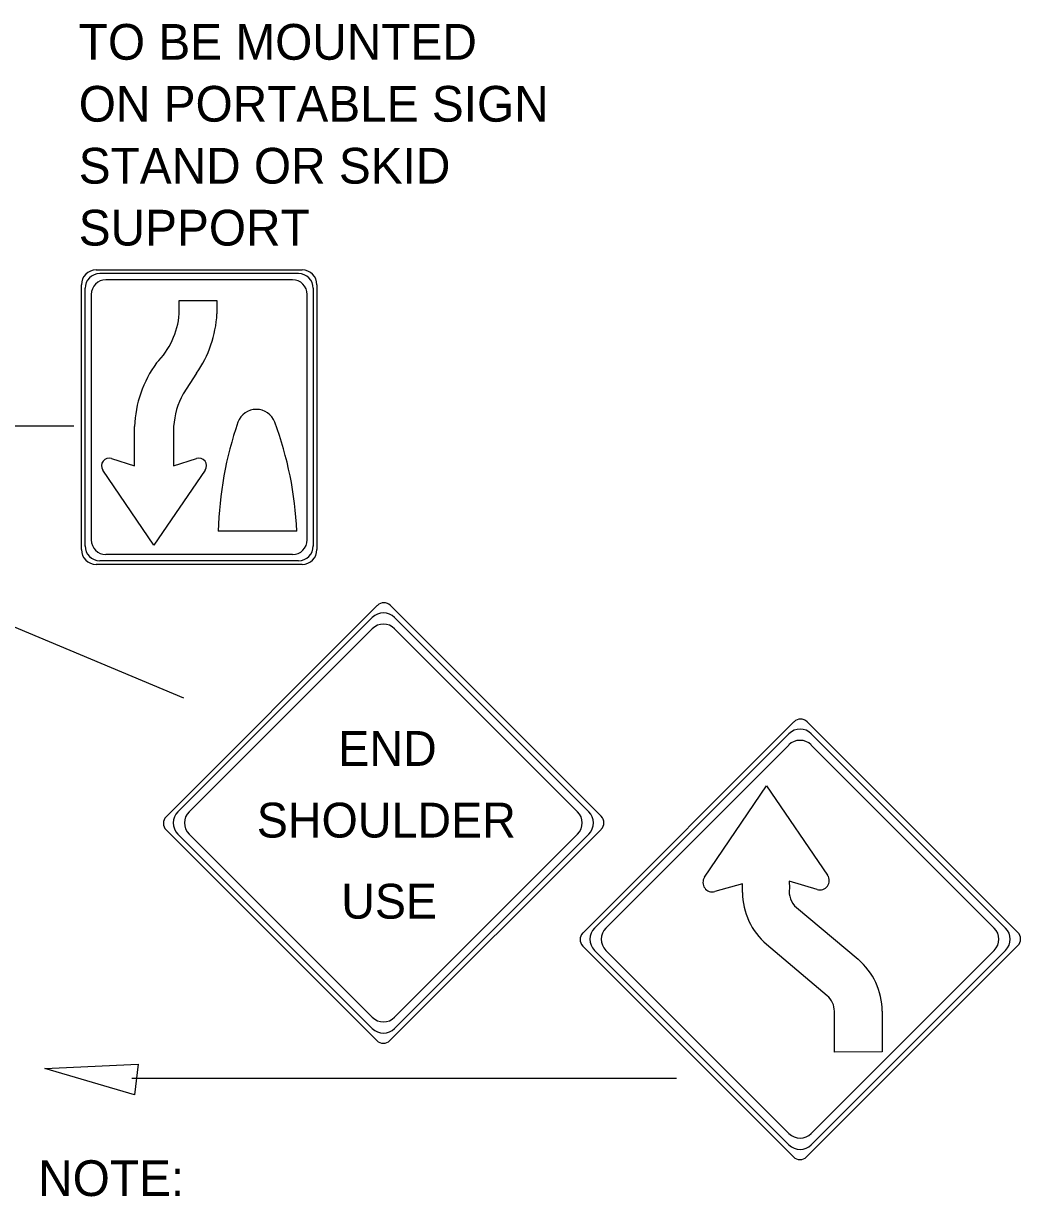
# Model space of a CAD drawing. Extents: x 1531.35 to 1538.58, y 1529.59 to 1539.23.
# Drawn here: x 1536.808 to 1538.482, y 1535.367 to 1537.337 of the extents above; entities that cross this region are included whole.
import ezdxf

# ---------------------------------------------------------------- set-up
doc = ezdxf.new("R2010")
doc.units = 0
for name, color, linetype in [('DETL-DIMS', 7, 'Continuous'), ('DETL-LINE', 7, 'Continuous'), ('DETL-NOTE', 7, 'Continuous')]:
    doc.layers.add(name, color=color, linetype=linetype)

msp = doc.modelspace()

# ---------------------------------------------------------------- linework, layer by layer
at = {"layer": 'DETL-DIMS'}
for p, q in [((1536.5902, 1536.6615), (1536.8925, 1536.6616)), ((1536.755, 1536.3393), (1537.0765, 1536.2049)), ((1537.9041, 1535.5657), (1536.9894, 1535.5658))]:
    msp.add_line(p, q, dxfattribs=at)
msp.add_lwpolyline([(1537.0003, 1535.5897), (1536.9941, 1535.5384), (1536.8433, 1535.5825)], close=True, dxfattribs=at)
at = {"layer": 'DETL-LINE'}
for p, q in [((1536.9296, 1536.9233), (1537.2757, 1536.9233)), ((1537.2696, 1536.9172), (1536.9359, 1536.9172)), ((1536.9049, 1536.4536), (1536.9049, 1536.8985)), ((1537.2592, 1536.9068), (1536.9461, 1536.9068)), ((1537.3004, 1536.8985), (1537.3004, 1536.4536)), ((1536.9112, 1536.4597), (1536.9112, 1536.8925)), ((1536.9214, 1536.8821), (1536.9214, 1536.4701)), ((1537.2839, 1536.4701), (1537.2839, 1536.8821)), ((1537.2943, 1536.8925), (1537.2943, 1536.4597)), ((1537.0694, 1536.872), (1537.1326, 1536.872)), ((1537.0694, 1536.8496), (1537.0694, 1536.872)), ((1537.1326, 1536.872), (1537.1326, 1536.8496)), ((1537.0982, 1536.7497), (1537.076, 1536.7151)), ((1536.9939, 1536.5945), (1536.9939, 1536.6604)), ((1537.0598, 1536.6604), (1537.0598, 1536.5945)), ((1536.9556, 1536.6069), (1536.994, 1536.5943)), ((1537.0598, 1536.5943), (1537.0982, 1536.6069)), ((1537.0268, 1536.4609), (1536.9408, 1536.5873)), ((1537.1129, 1536.5873), (1537.0268, 1536.4609)), ((1537.2666, 1536.4846), (1537.1348, 1536.4846)), ((1537.2592, 1536.4453), (1536.9461, 1536.4453)), ((1537.2757, 1536.4289), (1536.9296, 1536.4289)), ((1537.2696, 1536.435), (1536.9359, 1536.435)), ((1537.4018, 1536.3599), (1537.0471, 1536.0052)), ((1537.7777, 1536.0059), (1537.4238, 1536.3599)), ((1537.067, 1536.0135), (1537.3932, 1536.3397)), ((1537.4309, 1536.3397), (1537.757, 1536.0135)), ((1537.3932, 1536.3209), (1537.0859, 1536.0135)), ((1537.7382, 1536.0135), (1537.4308, 1536.3209)), ((1538.1015, 1536.1647), (1537.7468, 1535.8099)), ((1538.4774, 1535.8107), (1538.1235, 1536.1647)), ((1537.7667, 1535.8182), (1538.0929, 1536.1445)), ((1538.1306, 1536.1445), (1538.4567, 1535.8182)), ((1538.0929, 1536.1256), (1537.7856, 1535.8182)), ((1538.4379, 1535.8182), (1538.1305, 1536.1256)), ((1537.9512, 1535.9035), (1538.0554, 1536.0569)), ((1538.0554, 1536.0569), (1538.158, 1535.9068)), ((1537.7382, 1536.0135), (1537.7382, 1536.0135)), ((1537.0471, 1535.9832), (1537.401, 1535.6293)), ((1537.3932, 1535.6497), (1537.067, 1535.9758)), ((1537.0859, 1535.9759), (1537.3932, 1535.6685)), ((1537.423, 1535.6293), (1537.7777, 1535.984)), ((1537.757, 1535.9758), (1537.4309, 1535.6497)), ((1537.4309, 1535.6685), (1537.7382, 1535.9758)), ((1538.015, 1535.8925), (1537.9685, 1535.8795)), ((1538.015, 1535.8782), (1538.015, 1535.8925)), ((1538.0936, 1535.897), (1538.0941, 1535.8851)), ((1538.1405, 1535.8828), (1538.0936, 1535.897)), ((1538.1056, 1535.8525), (1538.2091, 1535.7659)), ((1538.4379, 1535.8182), (1538.4379, 1535.8182)), ((1537.7468, 1535.788), (1538.1008, 1535.4341)), ((1538.0929, 1535.4544), (1537.7667, 1535.7806)), ((1537.7856, 1535.7807), (1538.0929, 1535.4732)), ((1538.1575, 1535.7047), (1538.0556, 1535.7909)), ((1538.1227, 1535.4341), (1538.4774, 1535.7888)), ((1538.4567, 1535.7806), (1538.1306, 1535.4544)), ((1538.1306, 1535.4732), (1538.4379, 1535.7806)), ((1538.1696, 1535.61), (1538.1696, 1535.6786)), ((1538.2496, 1535.6787), (1538.2497, 1535.6102)), ((1538.2497, 1535.6102), (1538.1696, 1535.61))]:
    msp.add_line(p, q, dxfattribs=at)
for centre, radius, start, end in [((1536.9298, 1536.8985), 0.0247, 90, 180), ((1536.9359, 1536.8924), 0.0247, 90, 180), ((1537.2696, 1536.8924), 0.0247, 360, 90), ((1537.2758, 1536.8985), 0.0247, 360, 90), ((1536.9462, 1536.8821), 0.0247, 90, 180), ((1537.2594, 1536.8821), 0.0247, 360, 90), ((1536.937, 1536.861), 0.1329, 315.1307, 355.032), ((1536.937, 1536.861), 0.196, 325.3872, 356.6343), ((1537.1915, 1536.6516), 0.1977, 144.1907, 177.4446), ((1537.1915, 1536.6516), 0.1319, 151.1838, 176.1678), ((1537.1987, 1536.6561), 0.033, 20.3641, 159.6359), ((1537.7386, 1536.4703), 0.6039, 160.9328, 178.6381), ((1536.6646, 1536.4578), 0.6028, 2.5529, 20.3658), ((1536.9516, 1536.5945), 0.0129, 72, 214.2603), ((1537.1023, 1536.5945), 0.0129, 325.7397, 108), ((1536.9462, 1536.4701), 0.0247, 180, 270), ((1537.2594, 1536.4701), 0.0247, 270, 360), ((1536.9298, 1536.4536), 0.0247, 180, 270), ((1536.9359, 1536.4598), 0.0247, 180, 270), ((1537.2696, 1536.4598), 0.0247, 270, 360), ((1537.2758, 1536.4536), 0.0247, 270, 360), ((1537.4129, 1536.3489), 0.0155, 45, 135), ((1537.4121, 1536.3208), 0.0266, 45, 135), ((1537.4121, 1536.302), 0.0266, 45, 135), ((1538.1126, 1536.1537), 0.0155, 45, 135), ((1538.1118, 1536.1256), 0.0266, 45, 135), ((1538.1117, 1536.1068), 0.0266, 45, 135), ((1537.0859, 1535.9947), 0.0266, 135, 225), ((1537.1047, 1535.9947), 0.0266, 135, 225), ((1537.7194, 1535.9947), 0.0266, 315, 45), ((1537.7383, 1535.9947), 0.0266, 315, 45), ((1537.0582, 1535.9942), 0.0155, 135, 225), ((1537.7668, 1535.995), 0.0155, 315, 45), ((1537.9644, 1535.8947), 0.0157, 145.8336, 285.5836), ((1538.1451, 1535.8979), 0.0157, 253.1964, 34.3543), ((1538.1295, 1535.8783), 0.1144, 180.094, 229.7591), ((1538.1279, 1535.8787), 0.0343, 169.3489, 229.7591), ((1537.7856, 1535.7994), 0.0266, 135, 225), ((1537.8044, 1535.7995), 0.0266, 135, 225), ((1538.4191, 1535.7994), 0.0266, 315, 45), ((1538.438, 1535.7994), 0.0266, 315, 45), ((1537.7578, 1535.799), 0.0155, 135, 225), ((1538.4665, 1535.7998), 0.0155, 315, 45), ((1538.1352, 1535.6785), 0.1144, 0.094, 49.7591), ((1538.1352, 1535.6785), 0.0343, 0.094, 49.7591), ((1537.4121, 1535.6873), 0.0266, 225, 315), ((1537.4121, 1535.6685), 0.0266, 225, 315), ((1537.4121, 1535.6403), 0.0155, 225, 315), ((1538.1118, 1535.4921), 0.0266, 225, 315), ((1538.1118, 1535.4732), 0.0266, 225, 315), ((1538.1118, 1535.445), 0.0155, 225, 315)]:
    msp.add_arc(centre, radius, start, end, dxfattribs=at)

# ---------------------------------------------------------------- texts
for s, p in [('END', (1537.3364, 1536.0905)), ('SHOULDER', (1537.1995, 1535.9702)), ('USE', (1537.3413, 1535.834))]:
    msp.add_text(s, height=0.05854, dxfattribs=at).set_placement(p)
at = {"layer": 'DETL-NOTE'}
for s, p in [('TO BE MOUNTED', (1536.9005, 1537.2762)), ('ON PORTABLE SIGN', (1536.9005, 1537.1722)), ('STAND OR SKID', (1536.9005, 1537.0682)), ('SUPPORT', (1536.9005, 1536.9642)), ('NOTE:', (1536.8324, 1535.3683))]:
    msp.add_text(s, height=0.06, dxfattribs=at).set_placement(p)

doc.saveas('drawing.dxf')
